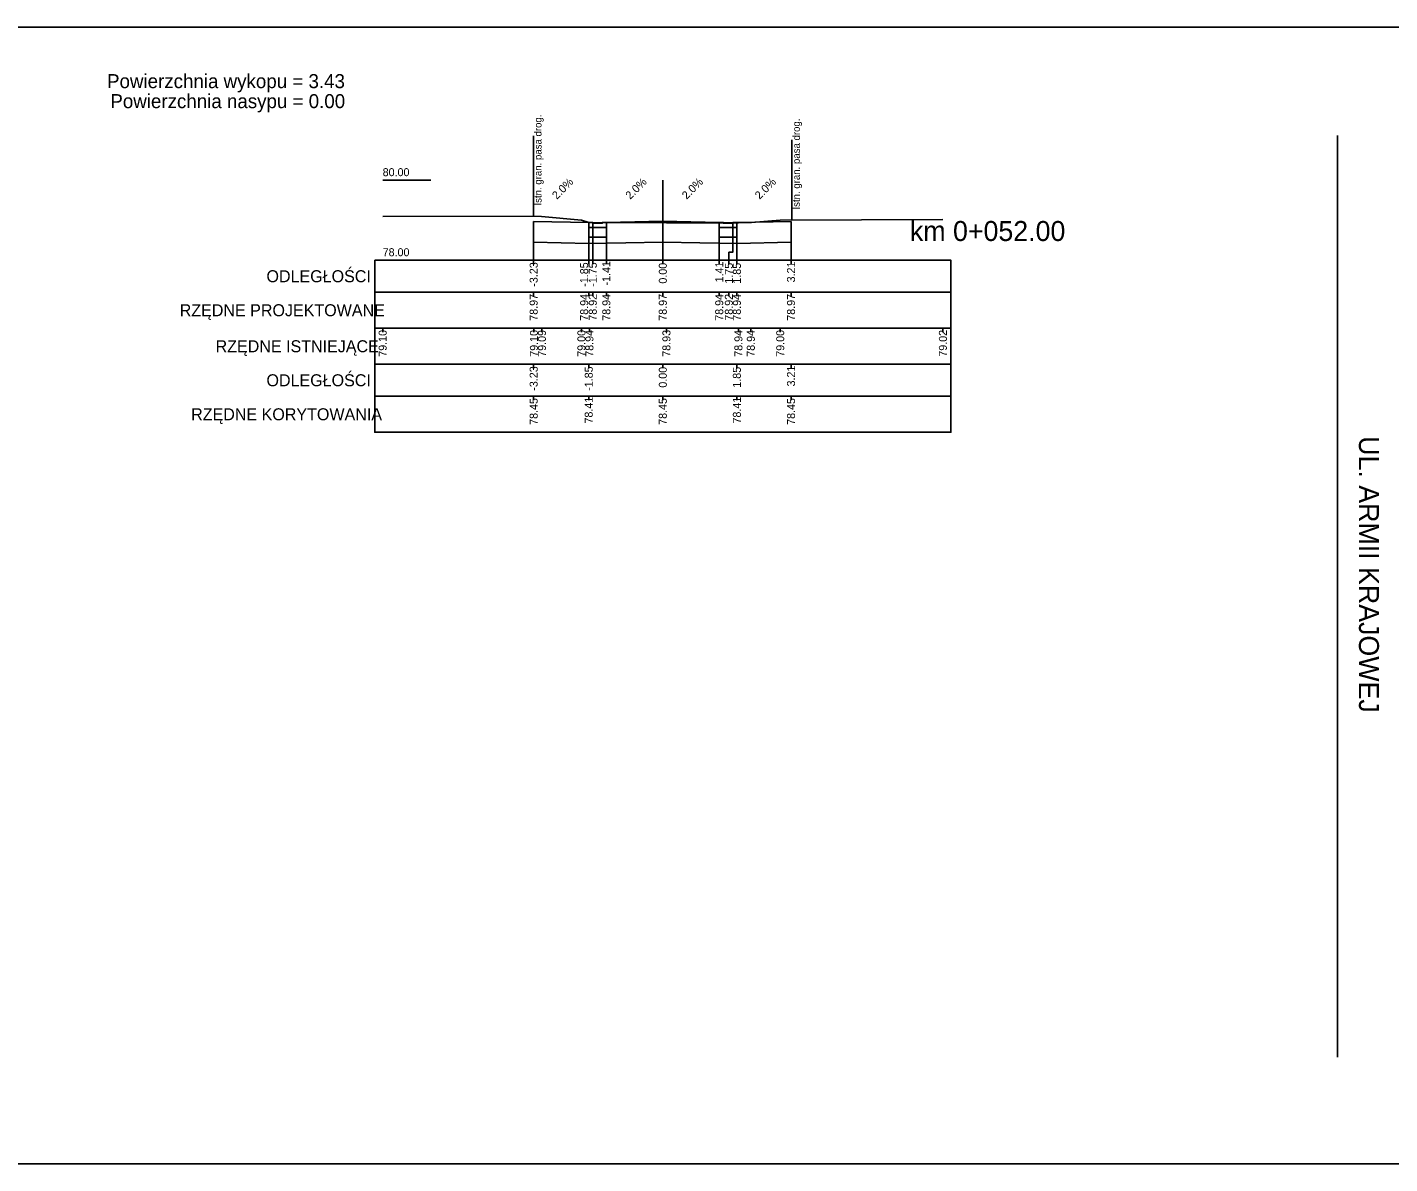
# Model space of a CAD drawing. Extents: x 7492871 to 7493499, y 5802964 to 5802992.
# Drawn here: x 7493195.61 to 7493229.66, y 5802963.88 to 5802992.28 of the extents above; entities that cross this region are included whole.
import ezdxf

# ---------------------------------------------------------------- set-up
doc = ezdxf.new("R2010")
doc.units = 0
for name, color, linetype in [('_wydruk', 7, 'Continuous'), ('d_pop_nasyp_opis', 7, 'Continuous'), ('d_pop_wykop_opis', 7, 'Continuous'), ('opisy_ramki_pop', 7, 'Continuous'), ('pop_comp_kostka', 7, 'Continuous'), ('pop_comp_lawa', 7, 'Continuous'), ('pop_comp_scieralna', 7, 'Continuous'), ('pop_granica_istn', 7, 'Continuous'), ('pop_opis', 7, 'Continuous'), ('pop_os', 7, 'Continuous'), ('pop_pikietaz', 7, 'Continuous'), ('pop_teren', 7, 'Continuous')]:
    doc.layers.add(name, color=color, linetype=linetype)

msp = doc.modelspace()

# ---------------------------------------------------------------- linework, layer by layer
msp.add_lwpolyline([(7493208.265, 5802987.43), (7493209.641, 5802987.403), (7493209.741, 5802987.403), (7493209.742, 5802987.383), (7493209.981, 5802987.383), (7493209.982, 5802987.403), (7493210.082, 5802987.403), (7493211.492, 5802987.431), (7493212.902, 5802987.403), (7493213.002, 5802987.403), (7493213.003, 5802987.383), (7493213.242, 5802987.383), (7493213.243, 5802987.403), (7493213.343, 5802987.403), (7493214.697, 5802987.43)])
at = {"layer": '_wydruk'}
msp.add_lwpolyline([(7492871.369, 5802992.281), (7493499.283, 5802992.281), (7493499.283, 5802963.881), (7492871.369, 5802963.881)], close=True, dxfattribs=at)
at = {"layer": 'opisy_ramki_pop'}
msp.add_line((7493228.355, 5802989.573), (7493228.355, 5802966.547), dxfattribs=at)
for points in [[(7493208.265, 5802986.91), (7493208.265, 5802986.659), (7493208.265, 5802986.659), (7493208.265, 5802986.459)], [(7493209.641, 5802986.874), (7493209.641, 5802986.659), (7493209.641, 5802986.659), (7493209.641, 5802986.459)], [(7493211.492, 5802986.911), (7493211.492, 5802986.659), (7493211.492, 5802986.659), (7493211.492, 5802986.459)], [(7493213.343, 5802986.874), (7493213.343, 5802986.659), (7493213.343, 5802986.659), (7493213.343, 5802986.459)], [(7493214.697, 5802986.91), (7493214.697, 5802986.659), (7493214.697, 5802986.659), (7493214.697, 5802986.459)]]:
    msp.add_lwpolyline(points, dxfattribs=at)
at = {"layer": 'pop_comp_kostka'}
for p, q in [((7493209.741, 5802987.403), (7493209.641, 5802987.403)), ((7493209.641, 5802987.403), (7493209.641, 5802987.273)), ((7493209.742, 5802987.383), (7493209.741, 5802987.403)), ((7493209.981, 5802987.383), (7493209.742, 5802987.383)), ((7493209.982, 5802987.403), (7493209.981, 5802987.383)), ((7493210.082, 5802987.403), (7493209.982, 5802987.403)), ((7493210.082, 5802987.273), (7493210.082, 5802987.403)), ((7493213.002, 5802987.403), (7493212.902, 5802987.403)), ((7493212.902, 5802987.403), (7493212.902, 5802987.273)), ((7493213.003, 5802987.383), (7493213.002, 5802987.403)), ((7493213.242, 5802987.383), (7493213.003, 5802987.383)), ((7493213.243, 5802987.403), (7493213.242, 5802987.383)), ((7493213.343, 5802987.403), (7493213.243, 5802987.403)), ((7493213.343, 5802987.273), (7493213.343, 5802987.403)), ((7493209.641, 5802987.273), (7493210.082, 5802987.273)), ((7493212.902, 5802987.273), (7493213.343, 5802987.273))]:
    msp.add_line(p, q, dxfattribs=at)
at = {"layer": 'pop_comp_lawa'}
for p, q in [((7493210.082, 5802987.273), (7493209.641, 5802987.273)), ((7493209.641, 5802987.273), (7493209.641, 5802987.032)), ((7493209.641, 5802987.032), (7493210.082, 5802987.032)), ((7493210.082, 5802987.032), (7493210.082, 5802987.273)), ((7493213.343, 5802987.273), (7493212.902, 5802987.273)), ((7493212.902, 5802987.273), (7493212.902, 5802987.032)), ((7493212.902, 5802987.032), (7493213.343, 5802987.032)), ((7493213.343, 5802987.032), (7493213.343, 5802987.273))]:
    msp.add_line(p, q, dxfattribs=at)
at = {"layer": 'pop_comp_scieralna'}
for p, q in [((7493209.641, 5802987.403), (7493208.265, 5802987.43)), ((7493208.265, 5802987.43), (7493208.265, 5802986.91)), ((7493209.641, 5802987.032), (7493209.641, 5802987.403)), ((7493211.492, 5802987.431), (7493210.082, 5802987.403)), ((7493210.082, 5802987.403), (7493210.082, 5802987.032)), ((7493211.492, 5802986.911), (7493211.492, 5802987.431)), ((7493212.902, 5802987.403), (7493211.492, 5802987.431)), ((7493211.492, 5802987.431), (7493211.492, 5802986.911)), ((7493212.902, 5802987.032), (7493212.902, 5802987.403)), ((7493214.697, 5802987.43), (7493213.343, 5802987.403)), ((7493213.343, 5802987.403), (7493213.343, 5802987.032)), ((7493214.697, 5802986.91), (7493214.697, 5802987.43)), ((7493210.082, 5802987.032), (7493209.641, 5802987.032)), ((7493213.343, 5802987.032), (7493212.902, 5802987.032)), ((7493208.265, 5802986.91), (7493209.641, 5802986.874)), ((7493209.641, 5802986.874), (7493211.492, 5802986.911)), ((7493211.492, 5802986.911), (7493213.343, 5802986.874)), ((7493213.343, 5802986.874), (7493214.697, 5802986.91))]:
    msp.add_line(p, q, dxfattribs=at)
at = {"layer": 'pop_granica_istn'}
for p, q in [((7493208.263, 5802988.064), (7493208.263, 5802989.564)), ((7493214.719, 5802987.964), (7493214.719, 5802989.464)), ((7493208.263, 5802987.564), (7493208.263, 5802988.064)), ((7493214.719, 5802987.464), (7493214.719, 5802987.964))]:
    msp.add_line(p, q, dxfattribs=at)
at = {"layer": 'pop_opis'}
for p, q in [((7493204.492, 5802988.459), (7493205.692, 5802988.459)), ((7493204.292, 5802986.459), (7493204.292, 5802984.759)), ((7493204.292, 5802986.459), (7493204.292, 5802984.759)), ((7493204.292, 5802986.459), (7493204.292, 5802984.759)), ((7493204.292, 5802986.459), (7493204.292, 5802984.759)), ((7493204.492, 5802986.459), (7493205.692, 5802986.459)), ((7493208.265, 5802986.359), (7493208.265, 5802986.459)), ((7493209.641, 5802986.359), (7493209.641, 5802986.459)), ((7493209.742, 5802986.359), (7493209.742, 5802986.459)), ((7493210.082, 5802986.359), (7493210.082, 5802986.459)), ((7493211.492, 5802986.359), (7493211.492, 5802986.459)), ((7493212.902, 5802986.359), (7493212.902, 5802986.459)), ((7493213.143, 5802986.359), (7493213.143, 5802986.459)), ((7493213.343, 5802986.359), (7493213.343, 5802986.459)), ((7493214.697, 5802986.359), (7493214.697, 5802986.459)), ((7493204.292, 5802985.659), (7493218.692, 5802985.659)), ((7493204.292, 5802985.659), (7493218.692, 5802985.659)), ((7493204.292, 5802985.659), (7493218.692, 5802985.659)), ((7493204.292, 5802985.659), (7493218.692, 5802985.659)), ((7493208.265, 5802985.559), (7493208.265, 5802985.659)), ((7493209.641, 5802985.559), (7493209.641, 5802985.659)), ((7493209.742, 5802985.559), (7493209.742, 5802985.659)), ((7493210.082, 5802985.559), (7493210.082, 5802985.659)), ((7493211.492, 5802985.559), (7493211.492, 5802985.659)), ((7493212.902, 5802985.559), (7493212.902, 5802985.659)), ((7493213.143, 5802985.559), (7493213.143, 5802985.659)), ((7493213.343, 5802985.559), (7493213.343, 5802985.659)), ((7493214.697, 5802985.559), (7493214.697, 5802985.659)), ((7493204.292, 5802984.759), (7493204.292, 5802983.859)), ((7493204.492, 5802984.659), (7493204.492, 5802984.759)), ((7493208.272, 5802984.659), (7493208.272, 5802984.759)), ((7493208.472, 5802984.659), (7493208.472, 5802984.759)), ((7493209.458, 5802984.659), (7493209.458, 5802984.759)), ((7493209.658, 5802984.659), (7493209.658, 5802984.759)), ((7493211.583, 5802984.659), (7493211.583, 5802984.759)), ((7493213.382, 5802984.659), (7493213.382, 5802984.759)), ((7493213.692, 5802984.659), (7493213.692, 5802984.759)), ((7493214.427, 5802984.659), (7493214.427, 5802984.759)), ((7493218.492, 5802984.659), (7493218.492, 5802984.759)), ((7493204.292, 5802983.859), (7493204.292, 5802982.159)), ((7493208.265, 5802983.759), (7493208.265, 5802983.859)), ((7493209.641, 5802983.759), (7493209.641, 5802983.859)), ((7493211.492, 5802983.759), (7493211.492, 5802983.859)), ((7493213.343, 5802983.759), (7493213.343, 5802983.859)), ((7493214.697, 5802983.759), (7493214.697, 5802983.859)), ((7493204.292, 5802983.059), (7493218.692, 5802983.059)), ((7493208.265, 5802982.959), (7493208.265, 5802983.059)), ((7493209.641, 5802982.959), (7493209.641, 5802983.059)), ((7493211.492, 5802982.959), (7493211.492, 5802983.059)), ((7493213.343, 5802982.959), (7493213.343, 5802983.059)), ((7493214.697, 5802982.959), (7493214.697, 5802983.059))]:
    msp.add_line(p, q, dxfattribs=at)
for points in [[(7493208.265, 5802987.43), (7493208.265, 5802986.659), (7493208.265, 5802986.659), (7493208.265, 5802986.459)], [(7493209.641, 5802987.403), (7493209.641, 5802986.659), (7493209.641, 5802986.659), (7493209.641, 5802986.459)], [(7493209.742, 5802987.383), (7493209.742, 5802986.659), (7493209.742, 5802986.659), (7493209.742, 5802986.459)], [(7493210.082, 5802987.403), (7493210.082, 5802986.659), (7493210.082, 5802986.659), (7493210.082, 5802986.459)], [(7493211.492, 5802987.431), (7493211.492, 5802986.659), (7493211.492, 5802986.659), (7493211.492, 5802986.459)], [(7493212.902, 5802987.403), (7493212.902, 5802986.659), (7493212.902, 5802986.659), (7493212.902, 5802986.459)], [(7493213.242, 5802987.383), (7493213.242, 5802986.659), (7493213.143, 5802986.659), (7493213.143, 5802986.459)], [(7493213.343, 5802987.403), (7493213.343, 5802986.659), (7493213.343, 5802986.659), (7493213.343, 5802986.459)], [(7493214.697, 5802987.43), (7493214.697, 5802986.659), (7493214.697, 5802986.659), (7493214.697, 5802986.459)]]:
    msp.add_lwpolyline(points, dxfattribs=at)
for points in [[(7493204.292, 5802986.459), (7493204.292, 5802984.759), (7493218.692, 5802984.759), (7493218.692, 5802986.459)], [(7493204.292, 5802986.459), (7493204.292, 5802984.759), (7493218.692, 5802984.759), (7493218.692, 5802986.459)], [(7493204.292, 5802986.459), (7493204.292, 5802984.759), (7493218.692, 5802984.759), (7493218.692, 5802986.459)], [(7493204.292, 5802986.459), (7493204.292, 5802984.759), (7493218.692, 5802984.759), (7493218.692, 5802986.459)], [(7493204.292, 5802984.759), (7493204.292, 5802983.859), (7493218.692, 5802983.859), (7493218.692, 5802984.759)], [(7493204.292, 5802983.859), (7493204.292, 5802982.159), (7493218.692, 5802982.159), (7493218.692, 5802983.859)]]:
    msp.add_lwpolyline(points, close=True, dxfattribs=at)
at = {"layer": 'pop_os'}
msp.add_line((7493211.492, 5802988.459), (7493211.492, 5802986.459), dxfattribs=at)
at = {"layer": 'pop_teren'}
msp.add_lwpolyline([(7493204.492, 5802987.554), (7493208.272, 5802987.564), (7493208.459, 5802987.548), (7493209.458, 5802987.463), (7493209.642, 5802987.401), (7493209.681, 5802987.401), (7493211.583, 5802987.394), (7493213.382, 5802987.397), (7493213.692, 5802987.399), (7493213.706, 5802987.399), (7493214.427, 5802987.462), (7493218.492, 5802987.48)], dxfattribs=at)

# ---------------------------------------------------------------- texts
at = {"layer": 'd_pop_nasyp_opis'}
msp.add_text('Powierzchnia nasypu = 0.00', height=0.35, dxfattribs=at).set_placement((7493197.687, 5802990.259))
at = {"layer": 'd_pop_wykop_opis'}
msp.add_text('Powierzchnia wykopu = 3.43', height=0.35, dxfattribs=at).set_placement((7493197.604, 5802990.759))
at = {"layer": 'pop_granica_istn'}
for p in [(7493208.461, 5802987.825), (7493214.918, 5802987.725)]:
    msp.add_text('Istn. gran. pasa drog.', height=0.18, rotation=90, dxfattribs=at).set_placement(p)
at = {"layer": 'pop_opis'}
for s, height, p in [('80.00', 0.2, (7493204.492, 5802988.559)), ('78.00', 0.2, (7493204.492, 5802986.559)), ('ODLEGŁOŚCI', 0.3, (7493201.588, 5802985.909)), ('ODLEGŁOŚCI', 0.3, (7493201.588, 5802985.909)), ('ODLEGŁOŚCI', 0.3, (7493201.588, 5802985.909)), ('ODLEGŁOŚCI', 0.3, (7493201.588, 5802985.909)), ('RZĘDNE PROJEKTOWANE', 0.3, (7493199.42, 5802985.059)), ('RZĘDNE PROJEKTOWANE', 0.3, (7493199.42, 5802985.059)), ('RZĘDNE PROJEKTOWANE', 0.3, (7493199.42, 5802985.059)), ('RZĘDNE PROJEKTOWANE', 0.3, (7493199.42, 5802985.059)), ('RZĘDNE ISTNIEJĄCE', 0.3, (7493200.317, 5802984.159)), ('ODLEGŁOŚCI', 0.3, (7493201.588, 5802983.309)), ('RZĘDNE KORYTOWANIA', 0.3, (7493199.706, 5802982.459))]:
    msp.add_text(s, height=height, dxfattribs=at).set_placement(p)
for s, rotation, p in [('2.0%', 45, (7493208.844, 5802987.966)), ('2.0%', 45, (7493210.678, 5802987.967)), ('2.0%', 45, (7493212.088, 5802987.967)), ('2.0%', 45, (7493213.911, 5802987.966)), ('-3.23', 90, (7493208.365, 5802985.798)), ('-1.85', 90, (7493209.627, 5802985.796)), ('-1.75', 90, (7493209.842, 5802985.796)), ('-1.41', 90, (7493210.182, 5802985.829)), ('0.00', 90, (7493211.592, 5802985.874)), ('1.41', 90, (7493213.002, 5802985.905)), ('1.75', 90, (7493213.243, 5802985.873)), ('1.85', 90, (7493213.443, 5802985.873)), ('3.21', 90, (7493214.797, 5802985.905)), ('78.97', 90, (7493208.365, 5802984.947)), ('78.94', 90, (7493209.627, 5802984.947)), ('78.92', 90, (7493209.842, 5802984.948)), ('78.94', 90, (7493210.182, 5802984.947)), ('78.97', 90, (7493211.592, 5802984.947)), ('78.94', 90, (7493213.002, 5802984.947)), ('78.92', 90, (7493213.243, 5802984.948)), ('78.94', 90, (7493213.443, 5802984.947)), ('78.97', 90, (7493214.797, 5802984.947)), ('79.10', 90, (7493204.592, 5802984.047)), ('79.10', 90, (7493208.372, 5802984.047)), ('79.09', 90, (7493208.572, 5802984.046)), ('79.00', 90, (7493209.558, 5802984.047)), ('78.94', 90, (7493209.758, 5802984.047)), ('78.93', 90, (7493211.683, 5802984.047)), ('78.94', 90, (7493213.482, 5802984.047)), ('78.94', 90, (7493213.792, 5802984.047)), ('79.00', 90, (7493214.527, 5802984.047)), ('79.02', 90, (7493218.592, 5802984.048)), ('-3.23', 90, (7493208.365, 5802983.198)), ('-1.85', 90, (7493209.741, 5802983.196)), ('0.00', 90, (7493211.592, 5802983.274)), ('1.85', 90, (7493213.443, 5802983.273)), ('3.21', 90, (7493214.797, 5802983.305)), ('78.45', 90, (7493208.365, 5802982.345)), ('78.41', 90, (7493209.741, 5802982.378)), ('78.45', 90, (7493211.592, 5802982.345)), ('78.41', 90, (7493213.443, 5802982.378)), ('78.45', 90, (7493214.797, 5802982.345))]:
    msp.add_text(s, height=0.2, rotation=rotation, dxfattribs=at).set_placement(p)
at = {"layer": 'pop_pikietaz'}
msp.add_text('km 0+052.00', height=0.5, dxfattribs=at).set_placement((7493217.668, 5802986.939))
msp.add_text('UL. ARMII KRAJOWEJ', height=0.5, rotation=270, dxfattribs=at).set_placement((7493228.889, 5802982.061))

doc.saveas('drawing.dxf')
